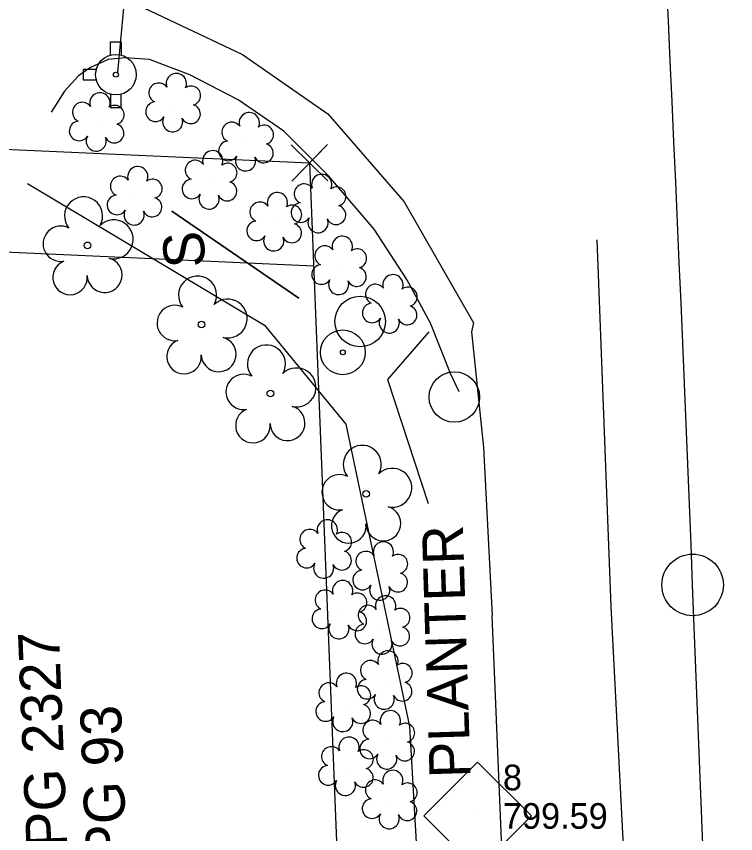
# Model space of a CAD drawing. Extents: x 1627482 to 1629573, y 760826 to 766301.
# Drawn here: x 1628285.6 to 1628355.8, y 764731.4 to 764811 of the extents above; entities that cross this region are included whole.
import ezdxf

# ---------------------------------------------------------------- set-up
doc = ezdxf.new("R2010")
doc.units = 0
for name, color, linetype in [('CTL Secondary Horizontal and Vertical CELL', 7, 'Continuous'), ('CTL Secondary Horizontal and Vertical Cogo Elevation', 7, 'Continuous'), ('CTL Secondary Horizontal and Vertical Cogo Number', 7, 'Continuous'), ('Default', 7, 'Continuous'), ('Exist Building', 7, 'Continuous'), ('Exist Building Leader', 7, 'Continuous'), ('Exist Building Text', 7, 'Continuous'), ('Exist Horizontal Alignment', 7, 'Continuous'), ('Exist Horizontal Alignment Point', 7, 'Continuous'), ('Exist Other Culture Sign', 7, 'Continuous'), ('Exist Other Culture Sign CELL', 7, 'Continuous'), ('Exist Other Culture Sign Text', 7, 'Continuous'), ('Exist Property Corner CELL', 7, 'Continuous'), ('Exist Property Deed Book Text', 7, 'Continuous'), ('Exist Right of Way Easement Line', 7, 'Continuous'), ('Exist Right of Way Line', 7, 'Continuous'), ('Exist Roads EOP', 7, 'Continuous'), ('Exist Roads EOT', 7, 'Continuous'), ('Exist Utilities Gas UG Line SUE LOS B', 7, 'Continuous'), ('Exist Utilities Other Located Object CELL', 7, 'Continuous'), ('Exist Utilities Other Pole CELL', 7, 'Continuous'), ('Exist Utilities Water Fire Hydrant CELL', 7, 'Continuous'), ('Exist Utilities Water UG Line SUE LOS B', 7, 'Continuous'), ('Exist Vegetation Shrub CELL', 7, 'Continuous'), ('Exist Vegetation Tree CELL', 7, 'Continuous')]:
    doc.layers.add(name, color=color, linetype=linetype)

# ---------------------------------------------------------------- blocks, each defined once
blk = doc.blocks.new('POINT_DISPLAY')
at = {"layer": 'Default'}
blk.add_line((0, 0), (0, 0), dxfattribs=at)
blk = doc.blocks.new('EXIST PROPERTY CORNER')
at = {"layer": 'Exist Property Corner CELL'}
blk.add_lwpolyline([(-3.81, 0), (3.81, 0), (0, 0), (0, 3.81), (0, -3.81)], dxfattribs=at)
blk.add_blockref('POINT_DISPLAY', (0, 0), dxfattribs=at)

msp = doc.modelspace()

# ---------------------------------------------------------------- linework, layer by layer
at = {"layer": 'CTL Secondary Horizontal and Vertical CELL'}
msp.add_line((1628330.563, 764733.082), (1628330.563, 764733.082), dxfattribs=at)
msp.add_lwpolyline([(1628325.348, 764733.1), (1628330.59, 764738.341), (1628335.84, 764733.091), (1628330.598, 764727.849)], close=True, dxfattribs=at)
at = {"layer": 'Exist Building'}
msp.add_line((1628328.797, 764774.423), (1628327.964, 764776.208), dxfattribs=at)
msp.add_lwpolyline([(1628327.964, 764776.208), (1628326.005, 764781.126), (1628323.676, 764785.385), (1628320.49, 764790.294), (1628316.053, 764795.471), (1628311.705, 764799.845), (1628307.227, 764802.877), (1628302.526, 764805.329), (1628298.601, 764806.807), (1628296.226, 764806.988), (1628294.545, 764806.818), (1628292.83, 764806.046), (1628291.662, 764805.215), (1628290.305, 764803.734), (1628289.001, 764801.671)], dxfattribs=at)
at = {"layer": 'Exist Building Leader'}
msp.add_lwpolyline([(1628325.85, 764780.281), (1628321.811, 764775.617), (1628325.77, 764763.554)], dxfattribs=at)
at = {"layer": 'Exist Horizontal Alignment'}
msp.add_line((1628461.178, 761975.875), (1628351.564, 764755.601), dxfattribs=at)
msp.add_arc((1620544.276, 764447.734), 7813.356, 2.2581898, 5.9470481, dxfattribs=at)
at = {"layer": 'Exist Horizontal Alignment Point'}
msp.add_circle((1628351.564, 764755.601), 3, dxfattribs=at)
at = {"layer": 'Exist Other Culture Sign'}
msp.add_line((1628300.773, 764792.041), (1628313.155, 764783.566), dxfattribs=at)
at = {"layer": 'Exist Other Culture Sign CELL'}
msp.add_line((1628313.155, 764783.566), (1628300.773, 764792.041), dxfattribs=at)
at = {"layer": 'Exist Right of Way Easement Line'}
msp.add_lwpolyline([(1628203.196, 764791.731), (1628257.814, 764789.277), (1628314.605, 764786.715)], dxfattribs=at)
at = {"layer": 'Exist Right of Way Line'}
msp.add_lwpolyline([(1628198.235, 764801.959), (1628258.263, 764799.262), (1628314.206, 764796.739), (1628318.393, 764691.374), (1628254.776, 764692.383), (1628196.957, 764693.301), (1628196.896, 764693.302)], dxfattribs=at)
at = {"layer": 'Exist Roads EOP'}
for points in [[(1628142.235, 764822.529), (1628186.228, 764820.972), (1628230.891, 764818.968), (1628274.652, 764816.717), (1628294.458, 764813.562), (1628307.664, 764807.306), (1628315.974, 764801.52), (1628323.429, 764792.947), (1628330.18, 764781.149), (1628330.009, 764780.26), (1628331.176, 764769.008), (1628332.004, 764752.618)], [(1628334.115, 764701.777), (1628332.004, 764752.618), (1628332.004, 764752.618)]]:
    msp.add_lwpolyline(points, dxfattribs=at)
at = {"layer": 'Exist Roads EOT'}
msp.add_lwpolyline([(1628346.242, 764702.373), (1628343.632, 764753.512), (1628342.253, 764789.225)], dxfattribs=at)
at = {"layer": 'Exist Utilities Gas UG Line SUE LOS B'}
msp.add_lwpolyline([(1628286.682, 764794.726), (1628309.806, 764780.926), (1628317.744, 764771.27), (1628323.951, 764741.798), (1628326.478, 764697.718), (1628324.401, 764689.297)], dxfattribs=at)
at = {"layer": 'Exist Utilities Other Located Object CELL'}
for radius in [2.18, 0.24]:
    msp.add_circle((1628317.445, 764778.272), radius, dxfattribs=at)
at = {"layer": 'Exist Utilities Other Pole CELL'}
for centre in [(1628319.135, 764781.278), (1628328.317, 764773.919)]:
    msp.add_circle(centre, 2.463, dxfattribs=at)
at = {"layer": 'Exist Utilities Water Fire Hydrant CELL'}
msp.add_line((1628295.312, 764805.338), (1628295.312, 764805.338), dxfattribs=at)
for points in [[(1628294.8, 764807.25), (1628294.8, 764808.538), (1628295.825, 764808.538), (1628295.825, 764807.225)], [(1628293.4, 764805.85), (1628292.112, 764805.85), (1628292.112, 764804.825), (1628293.4, 764804.825)], [(1628294.8, 764803.425), (1628294.8, 764802.138), (1628295.825, 764802.138), (1628295.825, 764803.45)]]:
    msp.add_lwpolyline(points, dxfattribs=at)
for radius in [1.977, 0.243]:
    msp.add_circle((1628295.312, 764805.338), radius, dxfattribs=at)
at = {"layer": 'Exist Utilities Water UG Line SUE LOS B'}
msp.add_line((1628297.2, 764823.774), (1628295.471, 764805.59), dxfattribs=at)
at = {"layer": 'Exist Vegetation Shrub CELL'}
for p, q in [((1628300.974, 764802.429), (1628300.974, 764802.429)), ((1628293.523, 764800.551), (1628293.523, 764800.551)), ((1628308.089, 764798.615), (1628308.089, 764798.615)), ((1628304.529, 764794.904), (1628304.529, 764794.904)), ((1628297.218, 764793.349), (1628297.218, 764793.349)), ((1628315.159, 764792.595), (1628315.159, 764792.595)), ((1628310.835, 764790.824), (1628310.835, 764790.824)), ((1628317.164, 764786.563), (1628317.164, 764786.563)), ((1628322.104, 764782.82), (1628322.104, 764782.82)), ((1628315.705, 764758.921), (1628315.705, 764758.921)), ((1628321.175, 764756.779), (1628321.175, 764756.779)), ((1628317.194, 764753.007), (1628317.194, 764753.007)), ((1628321.392, 764751.523), (1628321.392, 764751.523)), ((1628321.614, 764746.145), (1628321.614, 764746.145)), ((1628317.567, 764743.971), (1628317.567, 764743.971)), ((1628321.855, 764740.318), (1628321.855, 764740.318)), ((1628317.824, 764737.742), (1628317.824, 764737.742)), ((1628322.095, 764734.502), (1628322.095, 764734.502))]:
    msp.add_line(p, q, dxfattribs=at)
for centre, radius, start, end in [((1628301.203, 764804.47), 0.99, 334.83907, 200.47174), ((1628299.491, 764803.556), 0.968, 35.89076, 245.42165), ((1628302.646, 764803.298), 0.929, 284.45672, 126.08612), ((1628293.752, 764802.592), 0.99, 334.83907, 200.47174), ((1628292.04, 764801.678), 0.968, 35.89076, 245.42165), ((1628295.195, 764801.42), 0.929, 284.45672, 126.08612), ((1628299.174, 764801.725), 0.955, 95.10992, 327.95341), ((1628302.611, 764801.5), 0.937, 204.99133, 73.46012), ((1628308.318, 764800.655), 0.99, 334.83907, 200.47174), ((1628291.722, 764799.847), 0.955, 95.10992, 327.95341), ((1628300.846, 764800.746), 0.984, 151.27966, 21.38702), ((1628306.606, 764799.741), 0.968, 35.89076, 245.42165), ((1628295.16, 764799.622), 0.937, 204.99133, 73.46012), ((1628309.761, 764799.484), 0.929, 284.45672, 126.08612), ((1628293.394, 764798.867), 0.984, 151.27966, 21.38702), ((1628306.288, 764797.91), 0.955, 95.10992, 327.95341), ((1628309.726, 764797.686), 0.937, 204.99133, 73.46012), ((1628304.758, 764796.944), 0.99, 334.83907, 200.47174), ((1628307.96, 764796.931), 0.984, 151.27966, 21.38702), ((1628303.046, 764796.031), 0.968, 35.89076, 245.42165), ((1628306.201, 764795.773), 0.929, 284.45672, 126.08612), ((1628297.447, 764795.389), 0.99, 334.83907, 200.47174), ((1628295.735, 764794.476), 0.968, 35.89076, 245.42165), ((1628298.89, 764794.218), 0.929, 284.45672, 126.08612), ((1628302.728, 764794.2), 0.955, 95.10992, 327.95341), ((1628315.387, 764794.636), 0.99, 334.83907, 200.47174), ((1628306.166, 764793.975), 0.937, 204.99133, 73.46012), ((1628313.676, 764793.722), 0.968, 35.89076, 245.42165), ((1628316.831, 764793.464), 0.929, 284.45672, 126.08612), ((1628295.418, 764792.644), 0.955, 95.10992, 327.95341), ((1628304.4, 764793.22), 0.984, 151.27966, 21.38702), ((1628311.063, 764792.864), 0.99, 334.83907, 200.47174), ((1628298.855, 764792.42), 0.937, 204.99133, 73.46012), ((1628309.352, 764791.95), 0.968, 35.89076, 245.42165), ((1628312.507, 764791.693), 0.929, 284.45672, 126.08612), ((1628313.358, 764791.891), 0.955, 95.10992, 327.95341), ((1628297.09, 764791.665), 0.984, 151.27966, 21.38702), ((1628316.796, 764791.666), 0.937, 204.99133, 73.46012), ((1628309.034, 764790.119), 0.955, 95.10992, 327.95341), ((1628315.03, 764790.912), 0.984, 151.27966, 21.38702), ((1628312.472, 764789.895), 0.937, 204.99133, 73.46012), ((1628310.706, 764789.14), 0.984, 151.27966, 21.38702), ((1628317.393, 764788.603), 0.99, 334.83907, 200.47174), ((1628315.682, 764787.689), 0.968, 35.89076, 245.42165), ((1628318.836, 764787.431), 0.929, 284.45672, 126.08612), ((1628315.364, 764785.858), 0.955, 95.10992, 327.95341), ((1628318.801, 764785.634), 0.937, 204.99133, 73.46012), ((1628322.333, 764784.86), 0.99, 334.83907, 200.47174), ((1628317.036, 764784.879), 0.984, 151.27966, 21.38702), ((1628320.621, 764783.946), 0.968, 35.89076, 245.42165), ((1628323.776, 764783.689), 0.929, 284.45672, 126.08612), ((1628320.304, 764782.115), 0.955, 95.10992, 327.95341), ((1628323.741, 764781.891), 0.937, 204.99133, 73.46012), ((1628321.976, 764781.136), 0.984, 151.27966, 21.38702), ((1628315.934, 764760.961), 0.99, 334.83907, 200.47174), ((1628314.222, 764760.047), 0.968, 35.89076, 245.42165), ((1628317.377, 764759.789), 0.929, 284.45672, 126.08612), ((1628313.904, 764758.216), 0.955, 95.10992, 327.95341), ((1628321.404, 764758.819), 0.99, 334.83907, 200.47174), ((1628317.342, 764757.992), 0.937, 204.99133, 73.46012), ((1628319.692, 764757.906), 0.968, 35.89076, 245.42165), ((1628322.847, 764757.648), 0.929, 284.45672, 126.08612), ((1628315.576, 764757.237), 0.984, 151.27966, 21.38702), ((1628319.374, 764756.075), 0.955, 95.10992, 327.95341), ((1628322.812, 764755.85), 0.937, 204.99133, 73.46012), ((1628317.423, 764755.048), 0.99, 334.83907, 200.47174), ((1628321.046, 764755.095), 0.984, 151.27966, 21.38702), ((1628315.711, 764754.134), 0.968, 35.89076, 245.42165), ((1628318.866, 764753.876), 0.929, 284.45672, 126.08612), ((1628321.621, 764753.563), 0.99, 334.83907, 200.47174), ((1628319.909, 764752.65), 0.968, 35.89076, 245.42165), ((1628315.393, 764752.303), 0.955, 95.10992, 327.95341), ((1628318.831, 764752.078), 0.937, 204.99133, 73.46012), ((1628323.064, 764752.392), 0.929, 284.45672, 126.08612), ((1628317.065, 764751.324), 0.984, 151.27966, 21.38702), ((1628319.592, 764750.818), 0.955, 95.10992, 327.95341), ((1628323.029, 764750.594), 0.937, 204.99133, 73.46012), ((1628321.264, 764749.839), 0.984, 151.27966, 21.38702), ((1628321.843, 764748.186), 0.99, 334.83907, 200.47174), ((1628320.131, 764747.272), 0.968, 35.89076, 245.42165), ((1628323.286, 764747.014), 0.929, 284.45672, 126.08612), ((1628317.796, 764746.011), 0.99, 334.83907, 200.47174), ((1628319.814, 764745.441), 0.955, 95.10992, 327.95341), ((1628316.084, 764745.097), 0.968, 35.89076, 245.42165), ((1628319.239, 764744.839), 0.929, 284.45672, 126.08612), ((1628323.251, 764745.216), 0.937, 204.99133, 73.46012), ((1628321.486, 764744.462), 0.984, 151.27966, 21.38702), ((1628315.767, 764743.266), 0.955, 95.10992, 327.95341), ((1628319.204, 764743.042), 0.937, 204.99133, 73.46012), ((1628322.084, 764742.359), 0.99, 334.83907, 200.47174), ((1628317.439, 764742.287), 0.984, 151.27966, 21.38702), ((1628320.372, 764741.445), 0.968, 35.89076, 245.42165), ((1628323.527, 764741.187), 0.929, 284.45672, 126.08612), ((1628318.053, 764739.782), 0.99, 334.83907, 200.47174), ((1628320.055, 764739.614), 0.955, 95.10992, 327.95341), ((1628323.492, 764739.389), 0.937, 204.99133, 73.46012), ((1628316.342, 764738.868), 0.968, 35.89076, 245.42165), ((1628319.496, 764738.61), 0.929, 284.45672, 126.08612), ((1628321.726, 764738.634), 0.984, 151.27966, 21.38702), ((1628316.024, 764737.037), 0.955, 95.10992, 327.95341), ((1628319.462, 764736.813), 0.937, 204.99133, 73.46012), ((1628322.324, 764736.542), 0.99, 334.83907, 200.47174), ((1628317.696, 764736.058), 0.984, 151.27966, 21.38702), ((1628320.612, 764735.628), 0.968, 35.89076, 245.42165), ((1628323.767, 764735.37), 0.929, 284.45672, 126.08612), ((1628320.295, 764733.797), 0.955, 95.10992, 327.95341), ((1628323.732, 764733.573), 0.937, 204.99133, 73.46012), ((1628321.967, 764732.818), 0.984, 151.27966, 21.38702)]:
    msp.add_arc(centre, radius, start, end, dxfattribs=at)
at = {"layer": 'Exist Vegetation Tree CELL'}
for p, q in [((1628292.543, 764788.699), (1628292.543, 764788.699)), ((1628303.664, 764780.979), (1628303.664, 764780.979)), ((1628310.382, 764774.263), (1628310.382, 764774.263)), ((1628319.728, 764764.484), (1628319.728, 764764.484))]:
    msp.add_line(p, q, dxfattribs=at)
for centre in [(1628292.543, 764788.699), (1628303.664, 764780.979), (1628310.382, 764774.263), (1628319.728, 764764.484)]:
    msp.add_circle(centre, 0.326, dxfattribs=at)
for centre, radius, start, end in [((1628292.158, 764791.572), 1.856, 330.16508, 219.71335), ((1628295.092, 764789.287), 1.899, 257.1011, 134.19993), ((1628289.937, 764788.853), 1.727, 62.66361, 279.3457), ((1628290.839, 764785.578), 1.689, 111.56708, 6.23104), ((1628294.216, 764785.799), 1.698, 181.28216, 74.55999), ((1628303.279, 764783.852), 1.856, 330.16508, 219.71335), ((1628306.213, 764781.568), 1.899, 257.1011, 134.19993), ((1628301.059, 764781.133), 1.727, 62.66361, 279.3457), ((1628301.96, 764777.858), 1.689, 111.56708, 6.23104), ((1628305.337, 764778.08), 1.698, 181.28216, 74.55999), ((1628309.997, 764777.136), 1.856, 330.16508, 219.71335), ((1628312.93, 764774.852), 1.899, 257.1011, 134.19993), ((1628307.776, 764774.417), 1.727, 62.66361, 279.3457), ((1628308.677, 764771.142), 1.689, 111.56708, 6.23104), ((1628312.054, 764771.364), 1.698, 181.28216, 74.55999), ((1628319.343, 764767.358), 1.856, 330.16508, 219.71335), ((1628317.123, 764764.638), 1.727, 62.66361, 279.3457), ((1628322.277, 764765.073), 1.899, 257.1011, 134.19993), ((1628321.401, 764761.585), 1.698, 181.28216, 74.55999), ((1628318.024, 764761.363), 1.689, 111.56708, 6.23104)]:
    msp.add_arc(centre, radius, start, end, dxfattribs=at)

# ---------------------------------------------------------------- block references
at = {"layer": 'Exist Property Corner CELL', "xscale": 0.6561666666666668, "yscale": 0.6561666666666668, "rotation": 45.72460018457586}
msp.add_blockref('EXIST PROPERTY CORNER', (1628314.206, 764796.739), dxfattribs=at)

# ---------------------------------------------------------------- texts
at = {"layer": 'CTL Secondary Horizontal and Vertical Cogo Elevation'}
msp.add_text('799.59', height=2.5, dxfattribs=at).set_placement((1628333.063, 764731.832))
at = {"layer": 'CTL Secondary Horizontal and Vertical Cogo Number'}
msp.add_text('8', height=2.5, dxfattribs=at).set_placement((1628333.063, 764735.582))
at = {"layer": 'Exist Building Text'}
msp.add_text('PLANTER', height=4, rotation=91.77134, dxfattribs=at).set_placement((1628329.912, 764736.837))
at = {"layer": 'Exist Other Culture Sign Text'}
msp.add_text('S', height=4, rotation=93.6077, dxfattribs=at).set_placement((1628304.051, 764786.627))
at = {"layer": 'Exist Property Deed Book Text'}
for s, height, p in [('DB 2263 PG 2327', 3.99999, (1628291.461, 764707.751)), ('PB 8 PG 93', 4, (1628296.91, 764715.732))]:
    msp.add_text(s, height=height, rotation=92.25819, dxfattribs=at).set_placement(p)

doc.saveas('drawing.dxf')
